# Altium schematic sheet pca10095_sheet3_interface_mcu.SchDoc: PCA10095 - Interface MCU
size A3; Organization: Nordic Semiconductor; DocumentNumber: 3; SheetNumber: 3; SheetTotal: 6; CompanyName: Nordic Semiconductor
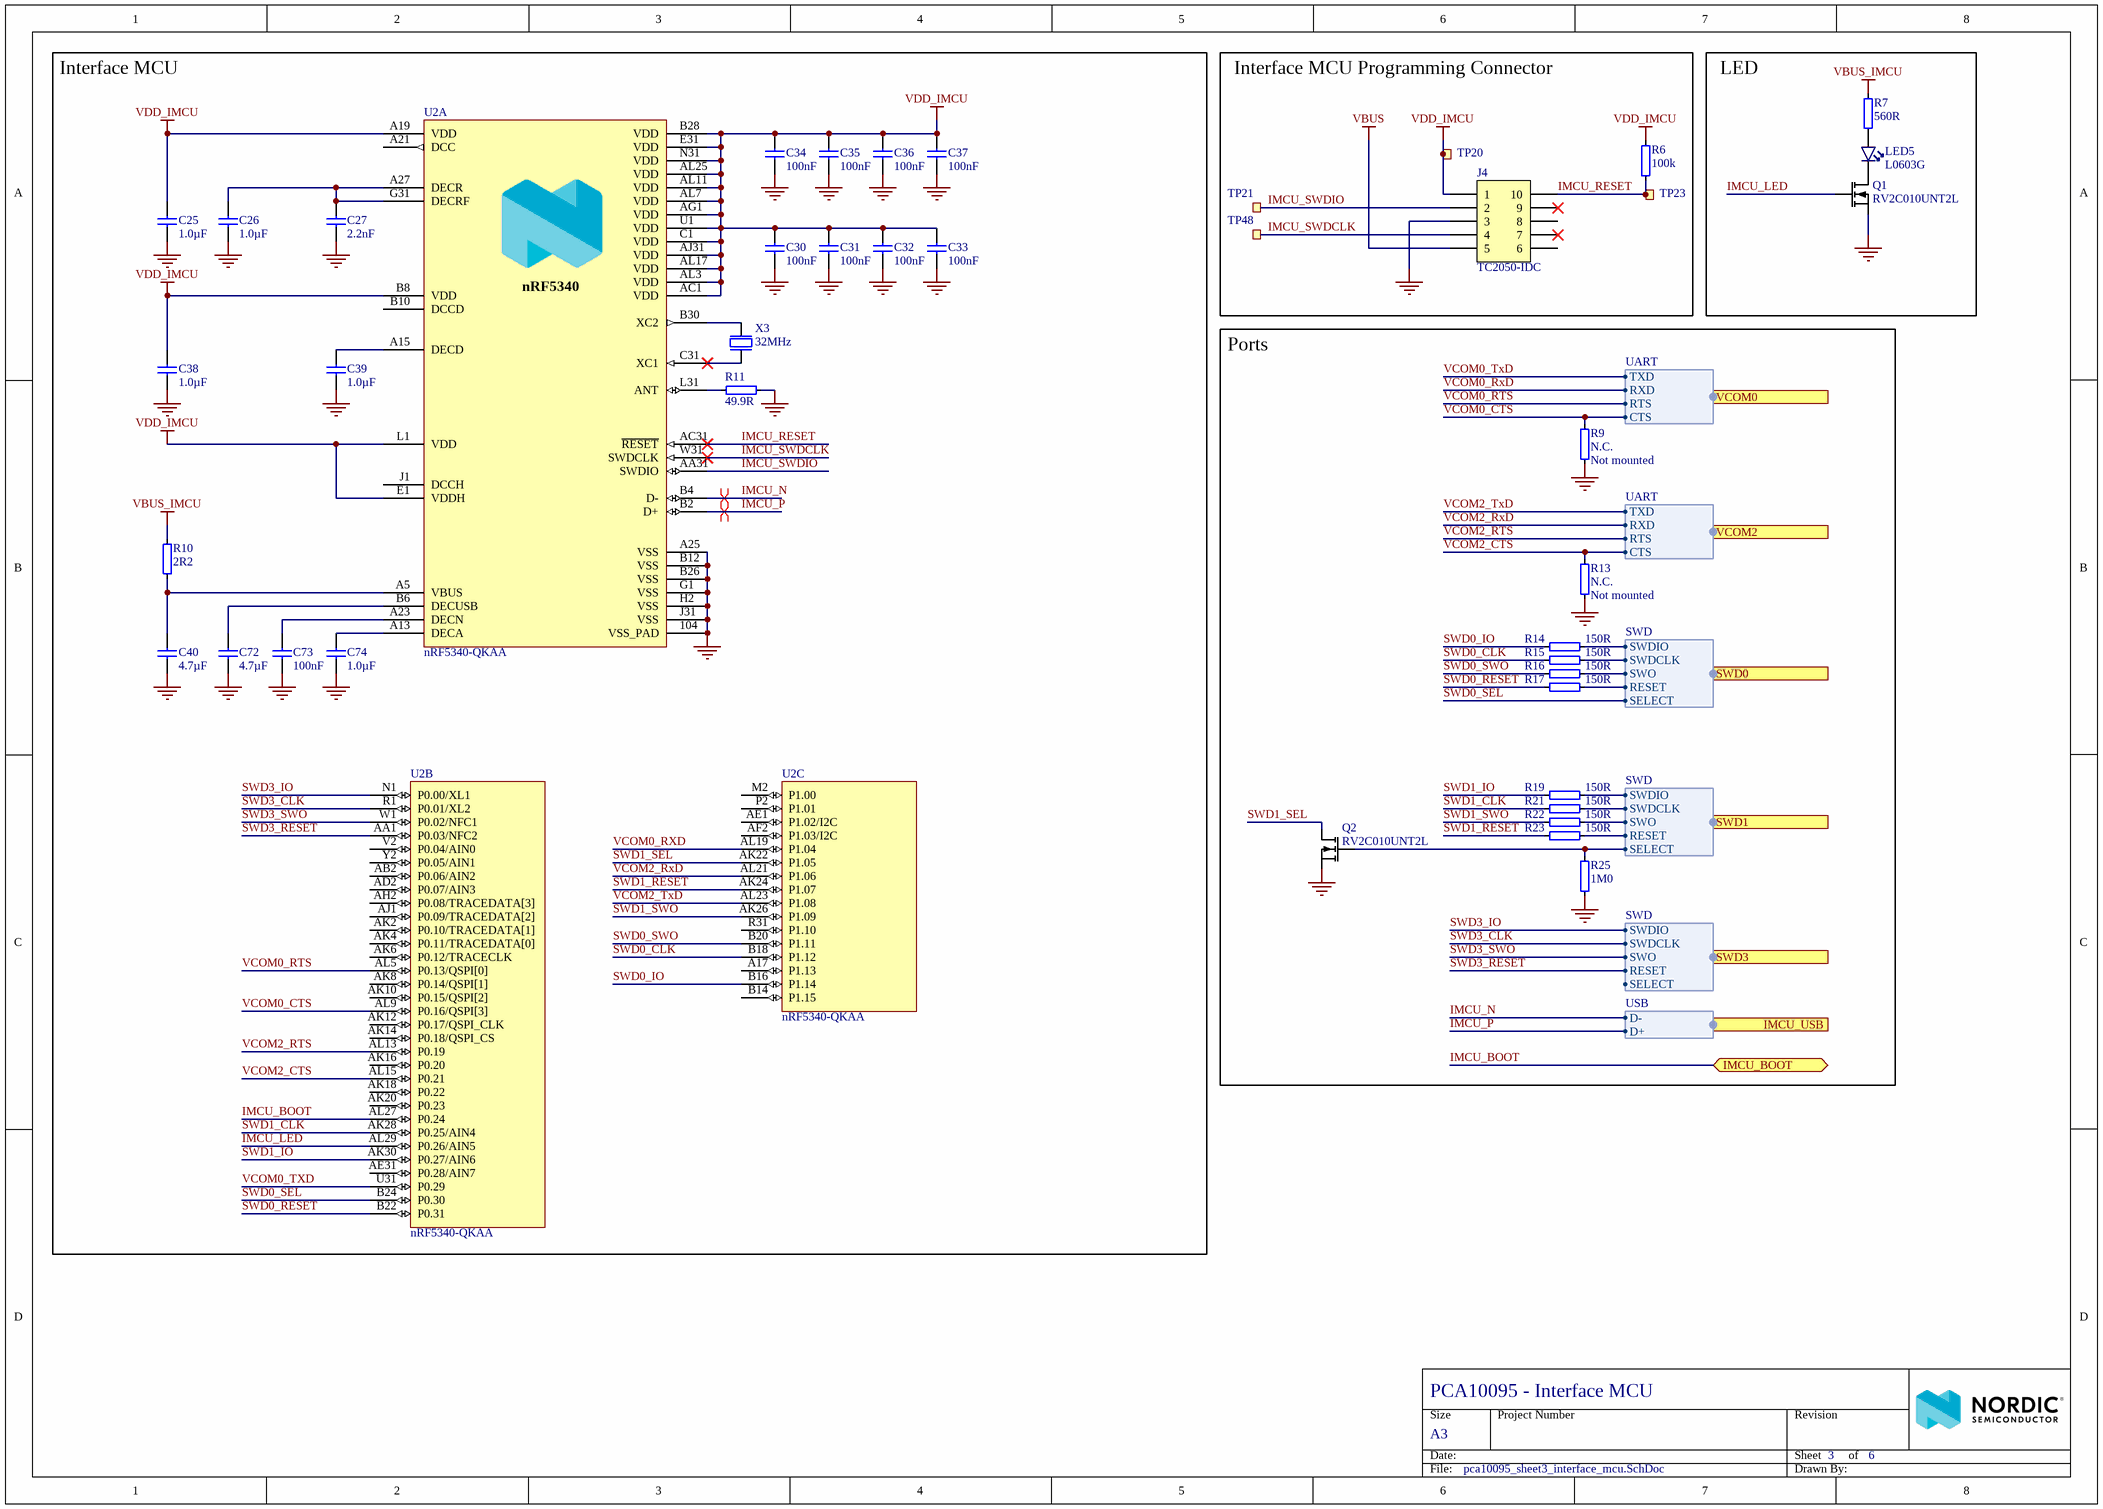
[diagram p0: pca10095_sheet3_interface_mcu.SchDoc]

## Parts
C25  1.0µF  [CAPC1005X04L]
C26  1.0µF  [CAPC1005X04L]
C27  2.2nF  [CAPC0603X03L_C]
C30  100nF  [CAPC0603X03L_C]
C31  100nF  [CAPC0603X03L_C]
C32  100nF  [CAPC0603X03L_C]
C33  100nF  [CAPC0603X03L_C]
C34  100nF  [CAPC0603X03L_C]
C35  100nF  [CAPC0603X03L_C]
C36  100nF  [CAPC0603X03L_C]
C37  100nF  [CAPC0603X03L_C]
C38  1.0µF  [CAPC1005X04L]
C39  1.0µF  [CAPC1005X04L]
C40  4.7µF  [CAPC1608X06L]
C72  4.7µF  [CAPC1608X06L]
C73  100nF  [CAPC0603X03L_C]
C74  1.0µF  [CAPC1005X04L]
J4  TC2050-IDC  [TC2050-IDC-NLFP]  (no BOM)
LED5  L0603G  [LED_0603_G]
Q1  RV2C010UNT2L  [DFN65P100X40-3L]
Q2  RV2C010UNT2L  [DFN65P100X40-3L]
R6  100k  [RESC0603X03L_C]
R7  560R  [RESC0603X03L_C]
R9  N.C.  Assembly: Not mounted  [RESC0603X03L_C_NC]
R10  2R2  [RESC0603X03L_C]
R11  49.9R  [RESC0603X03L_C]
R13  N.C.  Assembly: Not mounted  [RESC0603X03L_C_NC]
R14  150R  [RESC0603X03L_C]
R15  150R  [RESC0603X03L_C]
R16  150R  [RESC0603X03L_C]
R17  150R  [RESC0603X03L_C]
R19  150R  [RESC0603X03L_C]
R21  150R  [RESC0603X03L_C]
R22  150R  [RESC0603X03L_C]
R23  150R  [RESC0603X03L_C]
R25  1M0  [RESC0603X03L_C]
TP20  Ø1.5mm,SMD  [TP_SMD_Ø1.5mm]  (value not drawn)  (no BOM)
TP21  Ø1.5mm,SMD  [TP_SMD_Ø1.5mm]  (value not drawn)  (no BOM)
TP23  Ø1.5mm,SMD  [TP_SMD_Ø1.5mm]  (value not drawn)  (no BOM)
TP48  Ø1.5mm,SMD  [TP_SMD_Ø1.5mm]  (value not drawn)  (no BOM)
U2  nRF5340-QKAA  [AQFN40P700X700X85_HS-99N]  (parts A,B,C of 3)
X3  32MHz  [BT-XTAL_2016]

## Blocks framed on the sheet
Interface MCU: C25-C27 C30-C40 C72-C74 R10 R11 U2 X3
Interface MCU Programming Connector: J4 R6 TP20 TP21 TP23 TP48
LED: LED5 Q1 R7
Ports: Q2 R9 R13-R17 R19 R21-R23 R25

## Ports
IMCU_BOOT (bidir), IMCU_USB (harness USB), SWD0 (harness SWD), SWD1 (harness SWD), SWD3 (harness SWD), VCOM0 (harness UART), VCOM2 (harness UART)

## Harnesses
SWD: SWDIO, SWDCLK, SWO, RESET, SELECT
UART: RTS, CTS, RXD, TXD
USB: D+, D-

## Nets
GND: C25.2 C26.1 C27.2 C30.2 C31.2 C32.2 C33.2 C34.2 C35.2 C36.2 C37.2 C38.1 C39.1 C40.2 C72.2 C73.2 C74.1 J4.3 Q1.2(S) Q2.2(S) R9.2 R11.2 R13.2 R25.2 U2.104(VSS_PAD) U2.A25(VSS) U2.B12(VSS) U2.B26(VSS) U2.G1(VSS) U2.H2(VSS) U2.J31(VSS) X3.2(GND) X3.4(GND)
VBUS: J4.5
VBUS_IMCU: R7.2 R10.1
VDD_IMCU: C25.1 C30.1 C31.1 C32.1 C33.1 C34.1 C35.1 C36.1 C37.1 C38.2 J4.1 R6.2 TP20.1 U2.A19(VDD) U2.AC1(VDD) U2.AG1(VDD) U2.AJ31(VDD) U2.AL3(VDD) U2.AL7(VDD) U2.AL11(VDD) U2.AL17(VDD) U2.AL25(VDD) U2.B8(VDD) U2.B28(VDD) U2.C1(VDD) U2.E1(VDDH) U2.E31(VDD) U2.L1(VDD) U2.N31(VDD) U2.U1(VDD)
IMCU_BOOT: U2.AL27(P0.24) ; port IMCU_BOOT
IMCU_LED: Q1.1(G) U2.AL29(P0.26/AIN5)
IMCU_N: U2.B4(D-) ; port IMCU_USB.D-
IMCU_P: U2.B2(D+) ; port IMCU_USB.D+
IMCU_RESET: J4.10 R6.1 TP23.1 U2.AC31(~{RESET})
IMCU_SWDCLK: J4.4 TP48.1 U2.W31(SWDCLK)
IMCU_SWDIO: J4.2 TP21.1 U2.AA31(SWDIO)
SWD0_CLK: R15.1 U2.B18(P1.12)
SWD0_IO: R14.1 U2.B16(P1.14)
SWD0_RESET: R17.1 U2.B22(P0.31)
SWD0_SEL: U2.B24(P0.30) ; port SWD0.SELECT
SWD0_SWO: R16.1 U2.B20(P1.11)
SWD1_CLK: R21.1 U2.AK28(P0.25/AIN4)
SWD1_IO: R19.1 U2.AK30(P0.27/AIN6)
SWD1_RESET: R23.1 U2.AK24(P1.07)
SWD1_SEL: Q2.3(D) U2.AK22(P1.05)
SWD1_SWO: R22.1 U2.AK26(P1.09)
SWD3_CLK: U2.R1(P0.01/XL2) ; port SWD3.SWDCLK
SWD3_IO: U2.N1(P0.00/XL1) ; port SWD3.SWDIO
SWD3_RESET: U2.AA1(P0.03/NFC2) ; port SWD3.RESET
SWD3_SWO: U2.W1(P0.02/NFC1) ; port SWD3.SWO
VCOM0_CTS: R9.1 U2.AL9(P0.16/QSPI[3]) ; port VCOM0.CTS
VCOM0_RTS: U2.AL5(P0.13/QSPI[0]) ; port VCOM0.RTS
VCOM0_RXD: U2.AL19(P1.04) ; port VCOM0.RXD
VCOM0_TXD: U2.U31(P0.29) ; port VCOM0.TXD
VCOM2_CTS: R13.1 U2.AL15(P0.21) ; port VCOM2.CTS
VCOM2_RTS: U2.AL13(P0.19) ; port VCOM2.RTS
VCOM2_RxD: U2.AL21(P1.06) ; port VCOM2.RXD
VCOM2_TxD: U2.AL23(P1.08) ; port VCOM2.TXD
NetC26_2: C26.2 C27.1 U2.A27(DECR) U2.G31(DECRF)
NetC39_2: C39.2 U2.A15(DECD)
NetC40_1: C40.1 R10.2 U2.A5(VBUS)
NetC72_1: C72.1 U2.B6(DECUSB)
NetC73_1: C73.1 U2.A23(DECN)
NetC74_2: C74.2 U2.A13(DECA)
NetLED5_1: LED5.1(C) Q1.3(D)
NetLED5_2: LED5.2(A) R7.1
NetQ2_1: Q2.1(G) R25.1 ; port SWD1.SELECT
NetR11_1: R11.1 U2.L31(ANT)
NetR14_2: R14.2 ; port SWD0.SWDIO
NetR15_2: R15.2 ; port SWD0.SWDCLK
NetR16_2: R16.2 ; port SWD0.SWO
NetR17_2: R17.2 ; port SWD0.RESET
NetR19_2: R19.2 ; port SWD1.SWDIO
NetR21_2: R21.2 ; port SWD1.SWDCLK
NetR22_2: R22.2 ; port SWD1.SWO
NetR23_2: R23.2 ; port SWD1.RESET
NetU2_B30: U2.B30(XC2) X3.3(out)
NetU2_C31: U2.C31(XC1) X3.1(inp)

Not connected (* = marked no-connect by the designer): J4 6 7* 8 9*; U2 A17(P1.13) A21(DCC) AB2(P0.06/AIN2) AD2(P0.07/AIN3) AE1(P1.02/I2C) AE31(P0.28/AIN7) AF2(P1.03/I2C) AG31(N.C.) AH2(P0.08/TRACEDATA[3]) AJ1(P0.09/TRACEDATA[2]) AK2(P0.10/TRACEDATA[1]) AK4(P0.11/TRACEDATA[0]) AK6(P0.12/TRACECLK) AK8(P0.14/QSPI[1]) AK10(P0.15/QSPI[2]) AK12(P0.17/QSPI_CLK) AK14(P0.18/QSPI_CS) AK16(P0.20) AK18(P0.22) AK20(P0.23) B10(DCCD) B14(P1.15) D2(N.C.) F2(N.C.) J1(DCCH) M2(P1.00) P2(P1.01) R31(P1.10) T2(N.C.) V2(P0.04/AIN0) Y2(P0.05/AIN1)

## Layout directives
differential pair: IMCU_N, IMCU_P

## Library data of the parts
C25 C26 C38 C39 C74 = C0402-1µ0: Capacitor, X5R, ±5%, 6.3V; Manufacturer: N.A.; Part number IPS: 00000007786, 00000003457; Pad Count: 2; Artikkelnr Noca: 20039235
C27 = C0201-2n2: Capacitor, X7R, ±10%, 10V; Manufacturer: N.A.; Part number IPS: 00000001778; Pad Count: 2
C30-C37 C73 = C0201-100n: Capacitor, X5R, ±10%; Manufacturer: N.A.; Part number IPS: 00000001248, 00000002505; Pad Count: 2; Note: 16V
C40 = C0603-4µ7-10V-X7S: Capacitor, X7S, ±10%, 10V; Manufacturer: N.A.; Part number IPS: 00000001779; Pad Count: 2; Artikkelnr Noca: 20030013
C72 = C0603-4µ7-6.3V-X7R: Capacitor, X7R, ±10%, 6.3V; Manufacturer: Samsung Electro-Mechanics America; Manufacturer Part Number: CL10B475KQ8NQNC; Part number IPS: 00000002541; Part number Norautron: N.A.; Pad Count: 2; Artikkelnr Noca: 20039473
J4 = TC2050-IDC-NLFP: CBL PLUG-OF-NAILS 10-PIN; Manufacturer: Tag-Connect LLC; Artikkelnr Noca: N.A.; Pad Count: 10
LED5 = LG L29K Smartled Green: LED, Green, 0603, 570nm, Vf=1.7V, 2.24..5.6mcd, - 40 to +100°C; Manufacturer: Osram; Manufacturer Part Number: LG L29K-G2J1-24-Z; Part number IPS: 00000009961; Part number Norautron: N.A.; Note: 2.24..5.6 mcd, Vfmin=1.7V; Artikkelnr Noca: 13019147; Pad Count: 2
Q1 Q2 = RV2C010UNT2L: N-Channel MOSFET, 20V, 1A, 470mOhm, 400mW; Manufacturer: Rohm Semiconductor; Part number IPS: 00000009976; Note: N.A.; Artikkelnr Noca: 35010020; Pad Count: 3
R6 = R0201-100k: Resistor, ±1%, 0.05W; Manufacturer: N.A.; Part number IPS: 00000001419; Note: Chip Res 1%; Pad Count: 2
R7 = R0201-560: Resistor, ±1%, 0.05W; Manufacturer: N.A.; Note: Chip Res 1%; Pad Count: 2
R9 R13 = R0201-N.C.: Not mounted; Manufacturer: N.A.; Note: Chip Res; Pad Count: 2
R10 = R0201-2R2: Resistor, ±1%, 0.05W; Manufacturer: N.A.; Pad Count: 2; Note: Chip Res 1%
R11 = R0201-49R9: Resistor, ±1%, 0.05W; Manufacturer: N.A.; Pad Count: 2; Note: Chip Res 1%
R14-R17 R19 R21-R23 = R0201-150: Resistor, ±1%, 0.05W; Manufacturer: N.A.; Part number IPS: 00000001420; Note: Chip Res 1%; Pad Count: 2
R25 = R0201-1M0: Resistor, ±1%, 0.05W; Manufacturer: N.A.; Part number IPS: 00000001418; Note: Chip Res 1%; Pad Count: 2
TP20 TP21 TP23 TP48 = TP_SMD_Ø1.5MM: 1.5mm circular SMD testpad; Manufacturer: Nordic Semiconductor; Manufacturer Part Number: N.A.; Pad Count: 1
U2 = nRF5340-QKAAD0: Multi-protocol Bluetooth Low Energy, IEEE 802.15.4, ANT and 2.4GHz proprietary system-on-chip; Manufacturer: Nordic Semiconductor; Pad Count: 98; Note: N.A.
X3 = XTAL_SMD2016_32MHz_8pF_Golledge: XTAL SMD 2016, 32MHz, Cl=8pF, Tol: ±10ppm, Stab: ±15ppm; Manufacturer Part Number: MP06003; Part number IPS: 00000001431; Note: XTAL SMD 32.000MHz; Artikkelnr Noca: 22010050; Pad Count: 4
